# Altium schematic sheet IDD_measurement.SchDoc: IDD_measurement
size A3; DocumentNumber: MB1144; Revision: C-02; SheetNumber: 19; SheetTotal: 25; Project: STM32L476G-EVAL
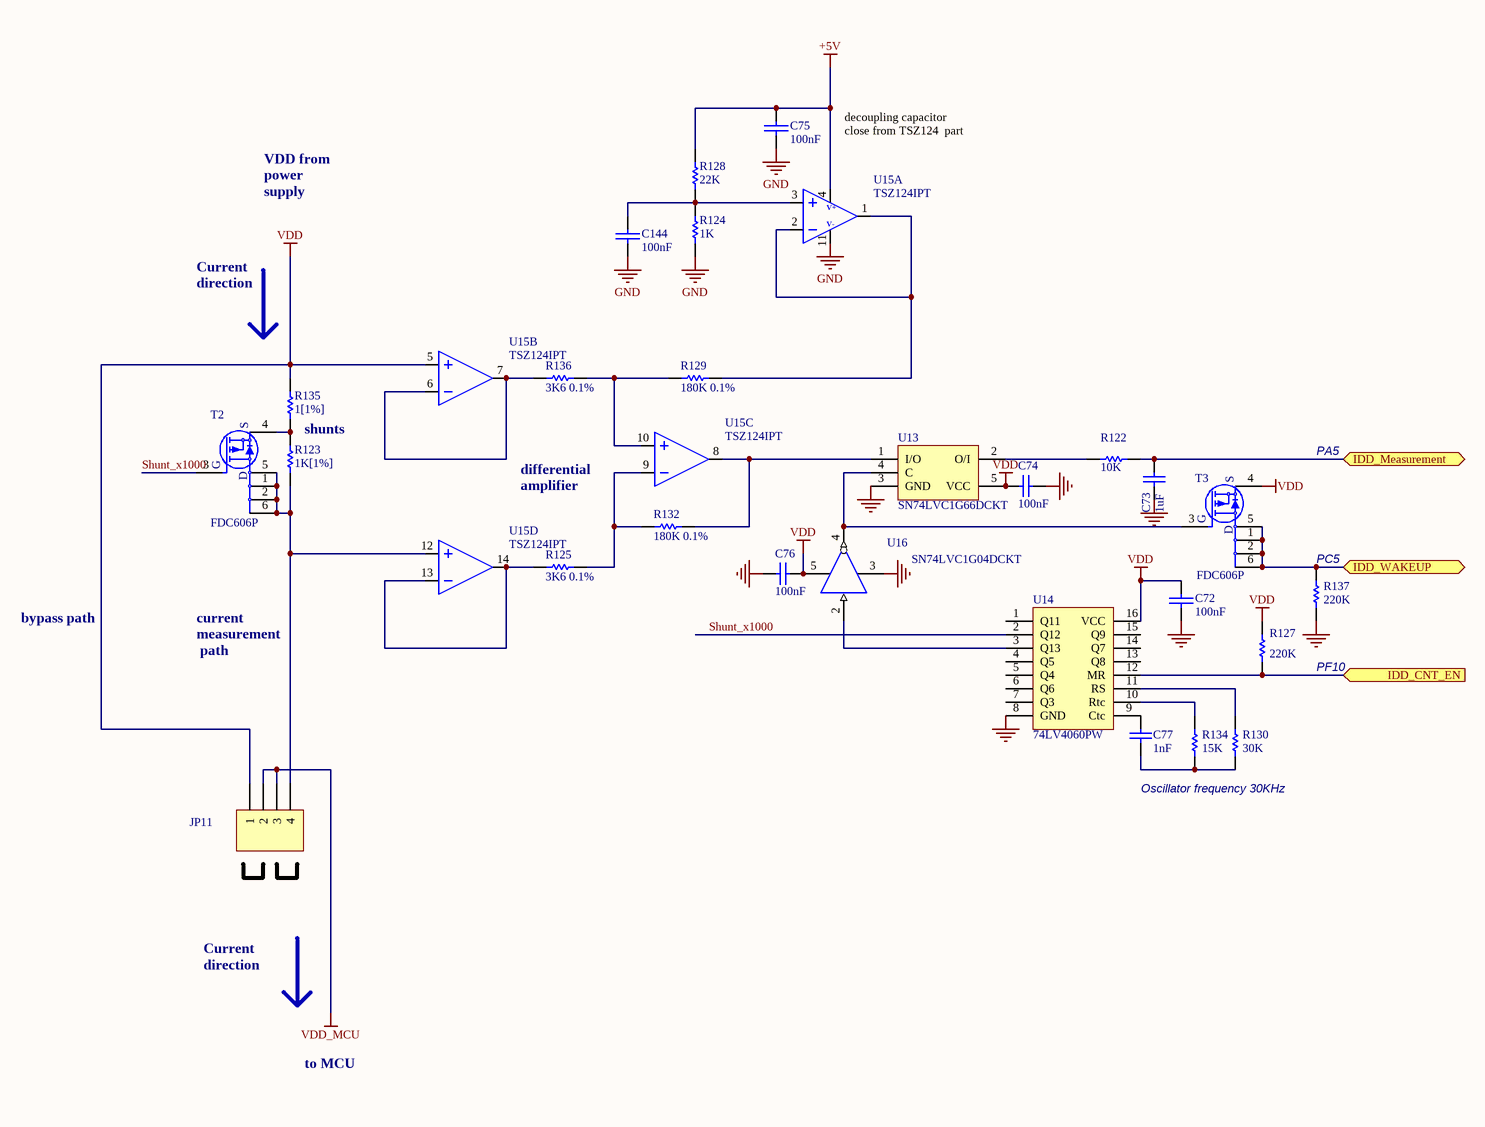
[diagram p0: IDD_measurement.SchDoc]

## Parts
C72  100nF  [0402C]
C73  1uF  [0603C]
C74  100nF  [0402C]
C75  100nF  [0402C]
C76  100nF  [0402C]
C77  1nF  [0402C]
C144  100nF  [0402C]
JP11  Header 4  [SIP4]  (value not drawn)
R122  10K  [0402R]
R123  1K[1%]  [0603R]
R124  1K  [0402R]
R125  3K6 0.1%  [0402R]
R127  220K  [0402R]
R128  22K  [0402R]
R129  180K 0.1%  [0402R]
R130  30K  [0402R]
R132  180K 0.1%  [0402R]
R134  15K  [0402R]
R135  1[1%]  [0603R]
R136  3K6 0.1%  [0402R]
R137  220K  [0402R]
T2  FDC606P  [SOT23-6]
T3  FDC606P  [SOT23-6]
U13  SN74LVC1G66DCKT  [SC70-5]
U14  74LV4060PW  [TSSOP16_0R65_5x6R4]
U15  TSZ124IPT  [TSSOP14_0R65_5X6R4]  (parts A,B,C,D of 4)
U16  SN74LVC1G04DCKT  [SC70-5]

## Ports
IDD_CNT_EN (in), IDD_Measurement, IDD_WAKEUP

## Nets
+5V: C75.1 R128.1 U15.4
GND: C72.2 C73.2 C74.1 C75.2 C76.2 C144.2 R124.2 R137.2 U13.3(GND) U14.8(GND) U15.11 U16.3(GND)
VDD: C72.1 C74.2 C76.1 JP11.1 R127.1 R135.2 T3.4(S) U13.5(VCC) U14.16(VCC) U15.5 U16.5(VCC)
VDD_MCU: JP11.2 JP11.3
IDD_CNT_EN: R127.2 U14.12(MR) ; port IDD_CNT_EN
IDD_Measurement: C73.1 R122.2 ; port IDD_Measurement
IDD_WAKEUP: R137.1 T3.1(D) T3.2(D) T3.5(D) T3.6(D) ; port IDD_WAKEUP
Shunt_x1000: T2.3(G) U14.2(Q12)
NetC77_1: C77.1 U14.9(Ctc)
NetC77_2: C77.2 R130.2 R134.2
NetC144_1: C144.1 R124.1 R128.2 U15.3
NetJP11_4: JP11.4 R123.1 T2.1(D) T2.2(D) T2.5(D) T2.6(D) U15.12
NetR122_1: R122.1 U13.2(O/I)
NetR123_2: R123.2 R135.1 T2.4(S)
NetR125_1: R125.1 U15.13 U15.14
NetR125_2: R125.2 R132.1 U15.9
NetR129_1: R129.1 R136.2 U15.10
NetR129_2: R129.2 U15.1 U15.2
NetR130_1: R130.1 U14.11(RS)
NetR132_2: R132.2 U13.1(I/O) U15.8
NetR134_1: R134.1 U14.10(Rtc)
NetR136_1: R136.1 U15.6 U15.7
NetT3_3: T3.3(G) U13.4(C) U16.4(1Y)
NetU14_3: U14.3(Q13) U16.2(1A)

Not connected (* = marked no-connect by the designer): U14 1(Q11) 4(Q5) 5(Q4) 6(Q6) 7(Q3) 13(Q8) 14(Q7) 15(Q9); U16 1(NC)

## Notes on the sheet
- decoupling capacitor
  close from TSZ124  part
- VDD from power supply
- Current direction
- shunts
- PA5
- differential
  amplifier
- (near R137) PC5
- bypass path
- current
  measurement
  path
- PF10
- Oscillator frequency 30KHz
- to MCU

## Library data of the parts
C72 C75 C144 = CAP: Ordered by: Subcon; ECCN_US/EU: NA
C73 = CAP: Capacitor; Value: 100nF; Ordered by: Subcon; ECCN_US/EU: NA
C74 C76 = CAP: Capacitor; Value: 100pF; Ordered by: Subcon; ECCN_US/EU: NA
C77 = Cap: Capacitor; Value: 10nF; Ordered by: Subcon; ECCN_US/EU: NA
JP11 = Header 4: Header, 4-Pin; Ordered by: Subcon
R122 R123 R125 R127-R130 R132 R134-R137 = res1: Resistor; Value: 1K; Ordered by: Subcon; ECCN_US/EU: NA
R124 = res1: Resistor; Ordered by: Subcon; ECCN_US/EU: NA
T2 T3 = STT5PF20V: Manuf_1: Fairchild; Ordered by: Subcon; ECCN_US/EU: EAR99/NEC
U13 = 74H1G66STR: Manuf_1: TI; Ordered by: Subcon; ECCN_US/EU: EAR99/NEC
U14 = M74HC4060TTR: Manuf_1: NXP; Ordered by: Subcon; ECCN_US/EU: EAR99/NEC
U15 = AOP-14PINS: Very high accuracy (5 µV) zero drift 5 V quad OpAmp; Ordered by: ST; ECCN_US/EU: EAR99/NEC; Ref St: 9177442
U16 = 74LX1G04CTR: Manuf_1: TI; Ordered by: Subcon; ECCN_US/EU: EAR99/NEC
